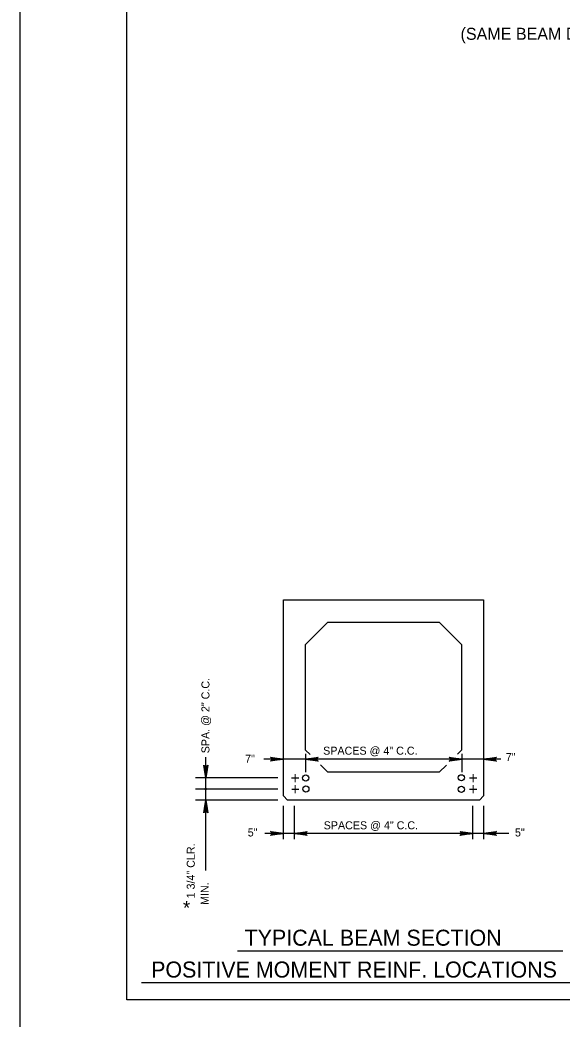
# Model space of a CAD drawing. Extents: x 641517 to 642372, y 298537 to 300319.
# Drawn here: x 641517 to 641720.5, y 299138.1 to 299512.8 of the extents above; entities that cross this region are included whole.
import ezdxf

# ---------------------------------------------------------------- set-up
doc = ezdxf.new("R2010")
doc.units = 0
for name, color, linetype in [('2', 7, 'Continuous'), ('3', 7, 'Continuous'), ('4', 7, 'Continuous'), ('PLT-BNDY', 7, 'Continuous')]:
    doc.layers.add(name, color=color, linetype=linetype)

msp = doc.modelspace()

# ---------------------------------------------------------------- linework, layer by layer
at = {"layer": '2'}
for p, q in [((641557.05, 299145.62), (641557.05, 299709.62)), ((641615.72, 299222.07), (641615.72, 299295.51)), ((641615.72, 299295.51), (641690.72, 299295.51)), ((641690.72, 299295.51), (641690.72, 299222.07)), ((641624.05, 299278.85), (641632.39, 299287.18)), ((641632.39, 299287.18), (641674.05, 299287.18)), ((641674.05, 299287.18), (641682.39, 299278.85)), ((641624.05, 299239.26), (641624.05, 299278.85)), ((641682.39, 299278.85), (641682.39, 299239.26)), ((641586.62, 299228.85), (641586.62, 299236.64)), ((641624.05, 299239.26), (641625.68, 299237.64)), ((641624.05, 299237.82), (641624.05, 299230.99)), ((641682.39, 299239.26), (641680.9, 299237.78)), ((641682.57, 299237.82), (641682.57, 299230.99)), ((641697.19, 299235.85), (641608.42, 299235.85)), ((641629.64, 299233.68), (641632.39, 299230.93)), ((641676.77, 299233.65), (641674.05, 299230.93)), ((641613.64, 299228.85), (641582.8, 299228.85)), ((641586.62, 299194.16), (641586.62, 299228.85)), ((641674.05, 299230.93), (641632.39, 299230.93)), ((641613.64, 299224.68), (641582.8, 299224.68)), ((641586.5, 299224.57), (641586.5, 299224.57)), ((641615.72, 299222.07), (641617.28, 299220.51)), ((641690.72, 299222.07), (641689.16, 299220.51)), ((641613.64, 299220.51), (641582.8, 299220.51)), ((641615.72, 299205.93), (641615.72, 299218.43)), ((641689.16, 299220.51), (641617.28, 299220.51)), ((641619.89, 299205.93), (641619.89, 299218.43)), ((641686.55, 299218.43), (641686.55, 299205.93)), ((641690.72, 299218.43), (641690.72, 299205.93)), ((641700.17, 299208.01), (641608.72, 299208.01)), ((641699.05, 299208.01), (641690.72, 299208.01)), ((641598.56, 299164.08), (641720.4, 299164.08)), ((641562.54, 299152.15), (641755.89, 299152.15)), ((642343.05, 299145.62), (641557.05, 299145.62))]:
    msp.add_line(p, q, dxfattribs=at)
for points in [[(641587, 299231.87), (641586.78, 299231.76), (641586.62, 299228.85), (641587, 299231.87), (641587.13, 299232.03), (641586.62, 299228.85), (641586.48, 299231.76), (641586.26, 299231.86), (641586.62, 299228.85), (641586.11, 299232.03), (641586.26, 299231.86)], [(641586.24, 299217.49), (641586.46, 299217.6), (641586.62, 299220.51), (641586.24, 299217.49), (641586.11, 299217.33), (641586.62, 299220.51), (641586.76, 299217.6), (641586.98, 299217.49), (641586.62, 299220.51), (641587.13, 299217.33), (641586.98, 299217.49)]]:
    msp.add_lwpolyline(points, dxfattribs=at)
at = {"layer": '3'}
for points in [[(641611.1, 299236.42), (641611.27, 299236.1), (641615.64, 299235.85), (641611.1, 299236.42), (641610.87, 299236.62), (641615.64, 299235.85), (641611.28, 299235.64), (641611.12, 299235.31), (641615.64, 299235.85), (641610.87, 299235.1), (641611.12, 299235.31)], [(641628.55, 299235.27), (641628.38, 299235.6), (641624, 299235.84), (641628.55, 299235.27), (641628.78, 299235.07), (641624, 299235.84), (641628.37, 299236.06), (641628.53, 299236.38), (641624, 299235.84), (641628.78, 299236.6), (641628.53, 299236.38)], [(641678.03, 299236.4), (641678.2, 299236.07), (641682.57, 299235.83), (641678.03, 299236.4), (641677.79, 299236.6), (641682.57, 299235.83), (641678.2, 299235.61), (641678.04, 299235.29), (641682.57, 299235.83), (641677.79, 299235.07), (641678.04, 299235.29)], [(641695.27, 299235.26), (641695.1, 299235.59), (641690.73, 299235.84), (641695.27, 299235.26), (641695.5, 299235.07), (641690.73, 299235.84), (641695.1, 299236.05), (641695.25, 299236.38), (641690.73, 299235.84), (641695.5, 299236.59), (641695.25, 299236.38)], [(641587.19, 299233.39), (641586.86, 299233.22), (641586.62, 299228.85), (641587.19, 299233.39), (641587.39, 299233.62), (641586.62, 299228.85), (641586.4, 299233.21), (641586.08, 299233.37), (641586.62, 299228.85), (641585.86, 299233.62), (641586.08, 299233.37)], [(641586.07, 299215.98), (641586.39, 299216.15), (641586.64, 299220.52), (641586.07, 299215.98), (641585.87, 299215.75), (641586.64, 299220.52), (641586.85, 299216.15), (641587.18, 299215.99), (641586.64, 299220.52), (641587.39, 299215.75), (641587.18, 299215.99)], [(641611.15, 299208.58), (641611.33, 299208.25), (641615.7, 299208.01), (641611.15, 299208.58), (641610.92, 299208.78), (641615.7, 299208.01), (641611.33, 299207.79), (641611.17, 299207.47), (641615.7, 299208.01), (641610.92, 299207.25), (641611.17, 299207.47)], [(641624.43, 299207.45), (641624.26, 299207.78), (641619.89, 299208.02), (641624.43, 299207.45), (641624.66, 299207.25), (641619.89, 299208.02), (641624.26, 299208.24), (641624.42, 299208.56), (641619.89, 299208.02), (641624.66, 299208.78), (641624.42, 299208.56)], [(641682.11, 299208.59), (641682.28, 299208.26), (641686.65, 299208.02), (641682.11, 299208.59), (641681.88, 299208.79), (641686.65, 299208.02), (641682.28, 299207.8), (641682.12, 299207.48), (641686.65, 299208.02), (641681.88, 299207.26), (641682.12, 299207.48)], [(641695.29, 299207.46), (641695.12, 299207.79), (641690.74, 299208.03), (641695.29, 299207.46), (641695.52, 299207.26), (641690.74, 299208.03), (641695.11, 299208.25), (641695.27, 299208.57), (641690.74, 299208.03), (641695.52, 299208.79), (641695.27, 299208.57)]]:
    msp.add_lwpolyline(points, dxfattribs=at)
msp.add_circle((641586.6, 299224.67), 0.324, dxfattribs=at)
at = {"layer": '4'}
for centre in [(641624.07, 299228.81), (641682.38, 299228.88), (641624.14, 299224.65), (641682.38, 299224.58)]:
    msp.add_circle(centre, 1.16, dxfattribs=at)
at = {"layer": 'PLT-BNDY'}
msp.add_lwpolyline([(641517.05, 299724.62), (642358.05, 299724.62), (642358.05, 299130.62), (641517.05, 299130.62)], close=True, dxfattribs=at)

# ---------------------------------------------------------------- texts
at = {"layer": '2'}
for s, height, p in [('(SAME BEAM DEPTH)', 4.5, (641682.07, 299505.41)), ('TYPICAL BEAM SECTION', 6, (641601.18, 299165.96)), ('POSITIVE MOMENT REINF. LOCATIONS', 6, (641566.16, 299154.03))]:
    msp.add_text(s, height=height, dxfattribs=at).set_placement(p)
at = {"layer": '3'}
for s, height, p in [('SPA. @ 2" C.C.', 2.999, (641588.01, 299238.07)), ('1 3/4" CLR.', 3, (641582.51, 299183.69)), ('MIN.', 3, (641587.7, 299181.24))]:
    msp.add_text(s, height=height, rotation=90, dxfattribs=at).set_placement(p)
for s, height, p in [('SPACES @ 4" C.C.', 2.999, (641630.61, 299237.54)), ('7"', 2.999, (641601.38, 299234.55)), ('7"', 2.999, (641699.02, 299235.13)), ('5"', 2.999, (641602.36, 299206.9)), ('SPACES @ 4" C.C.', 2.999, (641630.81, 299209.58)), ('5"', 2.999, (641702.46, 299206.9)), ('*', 5.18, (641578.1, 299177.57))]:
    msp.add_text(s, height=height, dxfattribs=at).set_placement(p)
at = {"layer": '4'}
for p in [(641618.45, 299226.68), (641685.14, 299226.68), (641618.47, 299222.5), (641685.14, 299222.5)]:
    msp.add_text('+', height=4.32, dxfattribs=at).set_placement(p)

doc.saveas('drawing.dxf')
